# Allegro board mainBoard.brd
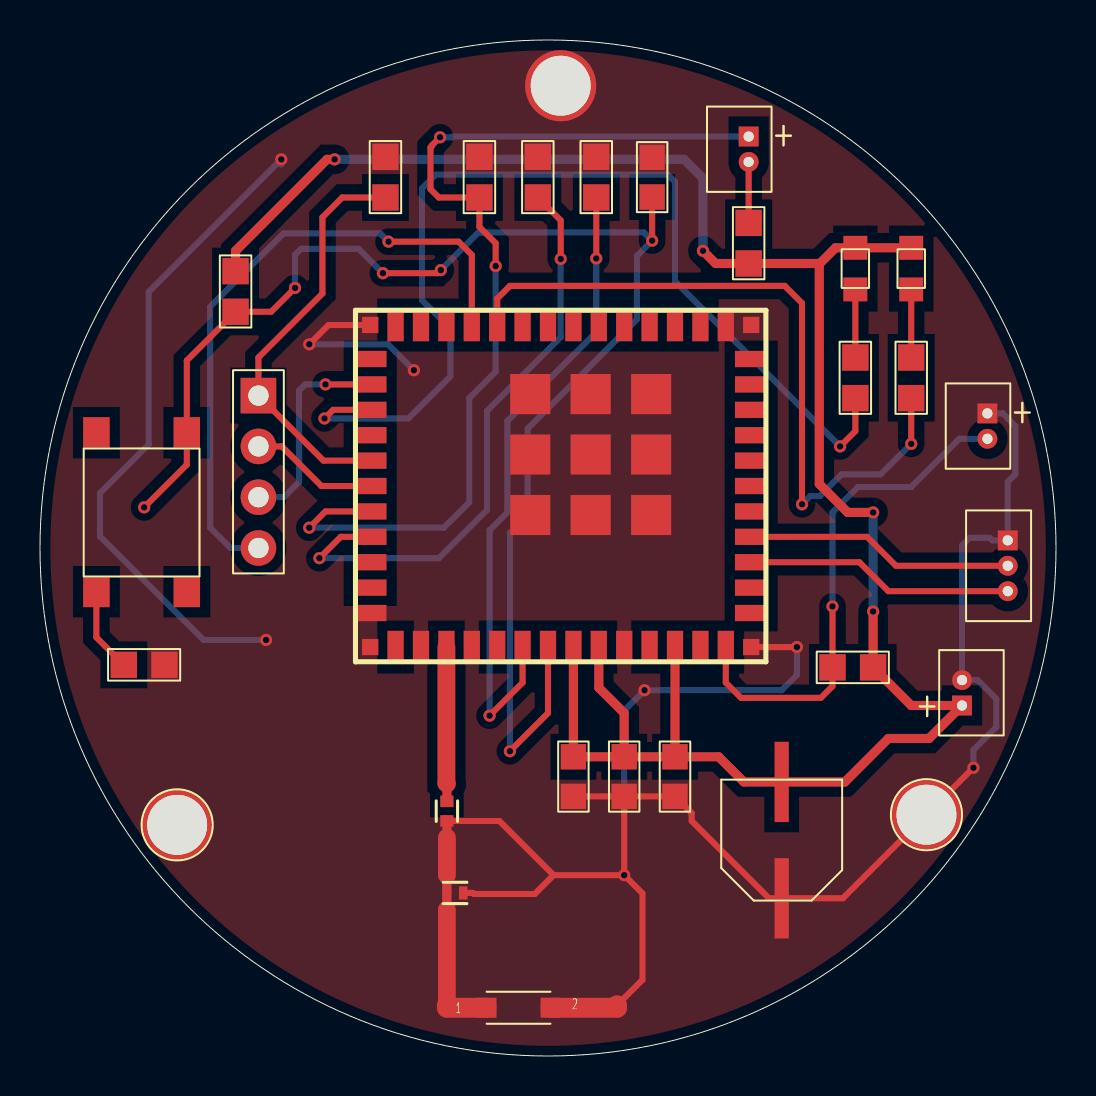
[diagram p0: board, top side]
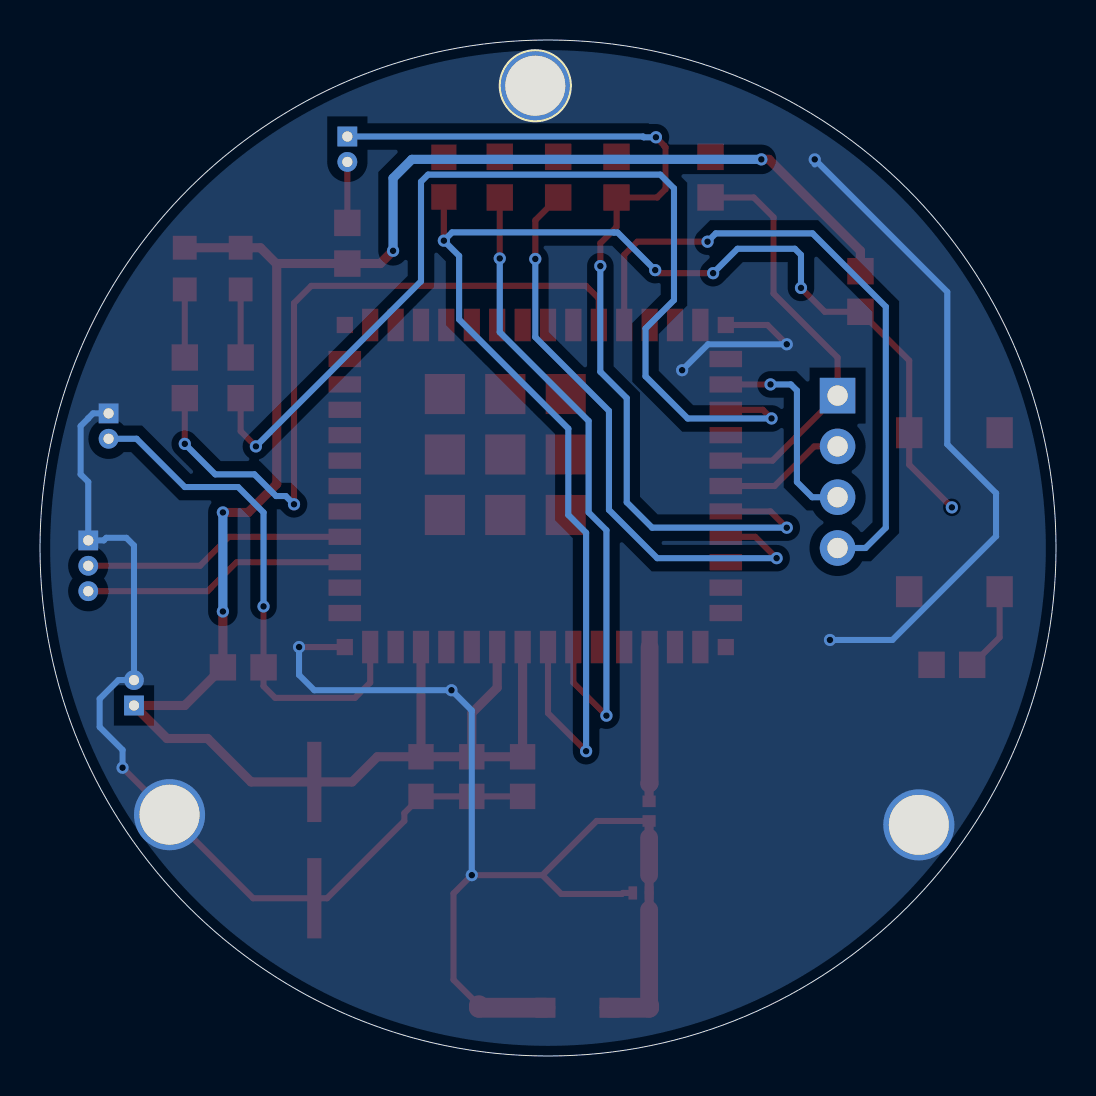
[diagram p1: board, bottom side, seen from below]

Outline 50.8 x 50.8 mm; copper layers: TOP, BOTTOM. Coordinates in mm from the lower left corner of the outline.
Outline path: circle c25.4,25.4 r25.4

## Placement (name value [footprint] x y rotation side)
C1  220uF/16V  [CAPPOL220U16V]  37.08 10.79 0 top
C2  0.1uF  [SMC0805]  29.21 13.97 270 top
C3  0.1uF  [SMC0805]  31.75 13.97 270 top
C4  1pF  [INDC_0402CS]  20.75 8.15 0 top
C5  0.1uF  [SMC0805]  30.61 43.94 90 top
C6  0.1uF  [SMC0805]  26.67 13.97 270 top
D1  -  [LED]  43.56 39.37 270 top
D2  -  [LED]  40.77 39.37 270 top
J1  HEADER 2  [HEADER21P25MM]  47.37 31.5 0 top
J2  HEADER 3  [HEADER31P25MM]  48.39 24.51 0 top
J3  HEADER 4  [HEADER42P54MM]  10.92 29.21 0 top
J4  HEADER 2  [HEADER21P25MM]  35.43 45.34 0 top
J5  HEADER 2  [HEADER21P25MM]  46.1 18.16 180 top
J6  HEADER 1  [HOLD]  44.32 12.06 0 top
J7  HEADER 1  [HOLD]  6.86 11.56 0 top
J8  HEADER 1  [HOLD]  26.04 48.51 180 bottom
L1  3.6nH  [CC0402]  20.35 12.24 270 top
R1  75  [SMR0805]  43.56 33.91 90 top
R2  75  [SMR0805]  40.77 33.91 90 top
R3  4.7K  [SMR0805]  9.78 38.23 270 top
R4  100R  [SMR0805]  5.21 19.56 0 top
R5  4.7K  [SMR0805]  35.43 40.64 90 top
R6  4.7K  [SMR0805]  40.64 19.43 180 top
R7  100K  [SMR0805]  17.27 43.94 90 top
R8  2.7K  [SMR0805]  21.97 43.94 90 top
R9  100K  [SMR0805]  24.89 43.94 90 top
R10  100K  [SMR0805]  27.81 43.94 90 top
S1  SW PUSHBUTTON  [BUTTON]  5.08 27.18 270 top
U1  -  [CC3200MOD]  35.56 20.45 0 top
U2  2.45-GHz Ant  [ANT_AH316M]  23.93 2.41 0 top

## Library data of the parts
C1 = CAPACITOR POL
C2-C6 = CAP NP
D1 D2 = LED_0
J1 J4 J5 = HEADER 2
J2 = HEADER 3
J3 = HEADER 4
J6-J8 = HEADER 1
L1 = INDUCTOR
R1-R4 R7-R10 = RESISTOR_0
R5 R6 = R
S1 = SW PUSHBUTTON
U1 = CC3200MOD_0
U2 = 2_0.45-GHz Ant

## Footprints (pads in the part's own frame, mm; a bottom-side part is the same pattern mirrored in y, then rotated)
ANT_AH316M
  rect 1.001x1.001 smd: 1(-1.6,0) 2(1.6,0)
BUTTON
  rect 1.549x1.321 smd: (-3.988,-2.261) (3.962,2.261) 1(-3.988,2.261) 2(3.962,-2.261)
CAPPOL220U16V
  rect 0.711x4.013 smd: 1(0,2.908) 2(0,-2.908)
CC0402
  rect 0.579x0.66 smd: 1(-0.49,0) 2(0.49,0)
CC3200MOD
  rect 0.813x0.813 smd: 1(0,16.104) 16(-19.05,16.104) 28(-19.05,0) 43(0,0)
  rect 0.813x1.626 smd: 2(-1.27,16.104) 3(-2.54,16.104) 4(-3.81,16.104) 5(-5.08,16.104) 6(-6.35,16.104) 7(-7.62,16.104) 8(-8.89,16.104) 9(-10.16,16.104) 10(-11.43,16.104) 11(-12.7,16.104) 12(-13.97,16.104) 13(-15.24,16.104) 14(-16.51,16.104) 15(-17.78,16.104) 29(-17.78,0) 30(-16.51,0) 31(-15.24,0) 32(-13.97,0) 33(-12.7,0) 34(-11.43,0) 35(-10.16,0) 36(-8.89,0) 37(-7.62,0) 38(-6.35,0) 39(-5.08,0) 40(-3.81,0) 41(-2.54,0) 42(-1.27,0)
  rect 1.626x0.813 smd: 17(-19.05,14.402) 18(-19.05,13.132) 19(-19.05,11.862) 20(-19.05,10.592) 21(-19.05,9.322) 22(-19.05,8.052) 23(-19.05,6.782) 24(-19.05,5.512) 25(-19.05,4.242) 26(-19.05,2.972) 27(-19.05,1.702) 44(0,1.702) 45(0,2.972) 46(0,4.242) 47(0,5.512) 48(0,6.782) 49(0,8.052) 50(0,9.322) 51(0,10.592) 52(0,11.862) 53(0,13.132) 54(0,14.402)
  rect 2.007x2.007 smd: 55(-5.004,12.649) 56(-8.026,12.649) 57(-11.049,12.649) 58(-5.004,9.627) 59(-8.026,9.627) 60(-11.049,9.627) 61(-5.004,6.604) 62(-8.026,6.604) 63(-11.049,6.604)
HEADER21P25MM
  rect 0.991x0.991 hole 0.508: 1(0,0.635)
  round 0.991 hole 0.508: 2(0,-0.635)
HEADER31P25MM
  rect 0.991x0.991 hole 0.508: 1(0,1.27)
  round 0.991 hole 0.508: 2(0,0) 3(0,-1.27)
HEADER42P54MM
  rect 1.778x1.778 hole 1.016: 1(0,3.81)
  round 1.778 hole 1.016: 2(0,1.27) 3(0,-1.27) 4(0,-3.81)
HOLD
  round 3.556 hole 2.997: 1(0,0)
INDC_0402CS
  rect 0.432x0.66 smd: 1(-0.409,0) 2(0.409,0)
LED
  rect 1.194x1.194 smd: 1(-1.041,0) 2(1.041,0)
SMC0805
  rect 1.27x1.27 smd: 1(-0.991,0) 2(0.991,0)
SMR0805
  rect 1.321x1.321 smd: 1(-1.016,0) 2(1.016,0)

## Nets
GND: C1.2 C2.2 C3.2 C4.1 C4.2 C5.2 C6.2 J1.1 J2.1 J5.2 J6.1 J7.1 J8.1 L1.2 R4.2 R7.2 R8.2 R9.2 R10.2 U1.1(GND2) U1.2(GND1) U1.16(GND18) U1.27(GND4) U1.28(GND7) U1.30(GND3) U1.32(GND8) U1.38(GND6) U1.43(GND5) U1.55(GND17) U1.56(GND16) U1.57(GND15) U1.58(GND14) U1.59(GND13) U1.60(GND12) U1.61(GND11) U1.62(GND10) U1.63(GND9) U2.1(IN) U2.2(GND)
VCC_3.3V: C1.1 C2.1 C3.1 C6.1 D1.1 D2.1 J5.1 R3.1 R5.1 R6.1 U1.36(VBAT_DCDC_ANA) U1.37(VBAT_DCDC_PA) U1.40(VBAT_DCDC_DIG_IO)
NLINK: R1.1 U1.11(GPIO22)
NREADY: R2.1 U1.19(GPIO28)
NRESET: C5.1 R3.2 S1.1 U1.35(NRESET)
SOP2: J4.1 R8.1 U1.23(TCXO_EN/SOP2)
SWITCH: J1.2 R6.2 U1.42(GPIO30)
UART0_RX: J2.2 U1.47(GPIO2)
UART0_TX: J2.3 U1.46(GPIO1)
N01152: R4.1 S1.2
N10829: J3.1 R7.1 U1.21(JTAG_TCK)
N10833: J3.2 U1.22(JTAG_TMS)
N10837: J3.3 U1.18(JTAG_TDO)
N10841: J3.4 U1.12(JTAG_TDI)
N12921: L1.1 U1.31(RF_BG)
N18108: R10.1 U1.34(SOP0)
N18112: R9.1 U1.24(SOP1)
N33058: J4.2 R5.2
N545706: D1.2 R1.2
N545710: D2.2 R2.2

Pads without a net: U1 3 4 5 6 7 8 9 10 13 14 15 17 20 25 26 29 33 39 41 44 45 48 49 50 51 52 53 54

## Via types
v1: diameter 0.61, hole 0.33, TOP to BOTTOM, 32 vias

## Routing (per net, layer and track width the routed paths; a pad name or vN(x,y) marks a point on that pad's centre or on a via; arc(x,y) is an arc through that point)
GND: length 154.3
  TOP w0.305: C2.2 v1(29.21,9.04) ; C2.2 C6.2 ; C2.2 C3.2 32.58,12.15 32.58,11.75 36.45,7.89 C1.2 40.14,7.89 J6.1 v1(46.67,14.41) ; v1(29.21,9.04) 25.68,9.04 ; v1(29.21,9.04) 30.12,8.13 30.12,3.81 28.85,2.54 ; 25.68,9.04 24.74,8.1 21.71,8.1 21.66,8.15 C4.2 ; 25.68,9.04 22.97,11.75 L1.2 ; v1(37.85,20.45) U1.43 ; v1(13.46,35.59) 14.43,36.55 U1.16 ; 24.89,47.37 J8.1
  TOP w0.457: 20.34,7.32 C4.1 20.34,9.04 20.35,9.04 ; L1.2 20.35,10.92
  TOP w0.889: 20.34,2.54 20.34,7.32 ; 20.35,10.92 20.35,9.04
  TOP w0.991: 28.85,2.54 28.85,2.41 U2.2 ; U2.1 20.34,2.41 20.34,2.54
  BOTTOM w0.305: v1(18.69,34.29) 17.4,35.59 v1(13.46,35.59) ; J1.1 48.15,32.13 48.39,31.89 48.39,31.88 48.77,31.5 48.77,29.08 48.39,28.7 J2.1 47.61,25.78 47.49,25.91 46.48,25.91 46.1,25.53 J5.2 46.88,18.8 47.82,17.86 47.82,16.45 46.67,15.3 v1(46.67,14.41) ; v1(37.85,20.45) 37.85,19.05 37.08,18.29 v1(30.23,18.29) 29.21,17.27 v1(29.21,9.04) ; v1(11.3,20.8) 8.18,20.8 3,25.98 3,28.14 5.44,30.58 5.44,38.2 v1(12.06,44.83) 12.06,44.58
VCC_3.3V: length 107.1
  TOP w0.457: 38.96,39.6 39.78,40.41 D2.1 D1.1 ; 38.96,39.6 38.94,39.62 R5.1 33.78,39.62 v1(33.15,40.26) ; 38.96,39.6 38.96,28.6 40.39,27.18 v1(41.66,27.18) ; U1.40 C3.1 ; C3.1 33.93,14.96 35.19,13.7 C1.1 40.25,13.7 42.42,15.87 44.45,15.87 J5.1 43.56,17.53 R6.1 v1(41.66,22.22) ; C3.1 C2.1 ; C2.1 29.21,17.14 27.94,18.41 U1.37 ; C2.1 C6.1 U1.36 ; v1(14.73,44.83) 14.35,44.83 9.78,40.26 R3.1
  BOTTOM w0.457: v1(14.73,44.83) 32.21,44.83 33.15,43.89 v1(33.15,40.26) ; v1(41.66,22.22) v1(41.66,27.18)
NLINK: length 36.2
  TOP w0.305: U1.11 22.86,37.87 23.49,38.51 37.24,38.51 38.1,37.64 v1(38.1,27.58) ; v1(43.56,30.61) R1.1
  BOTTOM w0.305: v1(43.56,30.61) 42.04,29.08 40.08,29.08 39,28 38.51,28 v1(38.1,27.58)
NREADY: length 52.1
  TOP w0.305: v1(14.22,31.88) 14.66,32.31 U1.19 ; v1(40,30.48) 40.77,31.24 R2.1
  BOTTOM w0.305: v1(14.22,31.88) 18.41,31.88 20.52,33.99 20.52,36.37 19.1,37.8 19.1,43.38 19.79,44.07 31.39,44.07 31.75,43.71 31.75,38.73 v1(40,30.48)
NRESET: length 72.9
  TOP w0.305: U1.35 25.4,17.14 v1(23.49,15.24) ; v1(30.61,40.77) C5.1 ; v1(17.14,39.14) 19.89,39.14 v1(20.04,39.29) ; v1(5.21,27.43) 7.34,29.57 S1.1 7.34,34.77 R3.2 11.56,37.21 v1(12.75,38.4)
  BOTTOM w0.305: v1(20.04,39.29) 21.92,41.17 22.1,41.17 22.11,41.18 30.19,41.18 v1(30.61,40.77) 29.84,40 29.84,36.83 24.38,31.37 24.38,27.05 23.49,26.16 v1(23.49,15.24) ; v1(12.75,38.4) 12.75,40.06 13.06,40.36 15.93,40.36 v1(17.14,39.14)
SOP2: length 48.9
  TOP w0.305: v1(13.46,26.42) 14.27,27.23 U1.23 ; v1(20,45.94) 19.59,45.52 19.59,45.5 19.52,45.43 19.52,43.34 19.94,42.93 R8.1 21.97,41.45 22.78,40.64 v1(22.78,39.5)
  BOTTOM w0.305: J4.1 20.65,45.97 20.61,45.94 v1(20,45.94) ; v1(13.46,26.42) 20.19,26.42 21.46,27.69 21.46,32.89 22.78,34.21 v1(22.78,39.5)
SWITCH: length 25.6
  TOP w0.305: U1.42 34.29,18.67 35.05,17.91 39.04,17.91 39.62,18.49 R6.2 v1(39.62,22.48)
  BOTTOM w0.305: J1.2 45.97,30.86 43.56,28.45 40.89,28.45 39.62,27.18 v1(39.62,22.48)
UART0_RX: length 13.4
  TOP w0.305: J2.2 42.8,24.51 41.35,25.96 U1.47
UART0_TX: length 13.4
  TOP w0.305: U1.46 40.97,24.69 42.42,23.24 J2.3
N01152: length 4.2
  TOP w0.305: S1.2 2.82,20.93 4.19,19.56
N10829: length 20.7
  TOP w0.305: R7.1 15.11,42.93 14.12,41.94 14.12,38.13 10.92,34.92 J3.1 14.17,29.77 U1.21
N10833: length 6.4
  TOP w0.305: J3.2 12.09,30.48 14.07,28.5 U1.22
N10837: length 10.6
  TOP w0.305: U1.18 v1(14.27,33.58)
  BOTTOM w0.305: J3.3 12.19,27.94 12.95,28.7 12.95,33.27 13.26,33.58 v1(14.27,33.58)
N10841: length 32.4
  TOP w0.305: v1(17.42,40.72) 20.93,40.72 21.59,40.06 U1.12
  BOTTOM w0.305: J3.4 9.52,25.4 8.51,26.42 8.51,37.46 12.17,41.13 17.01,41.13 v1(17.42,40.72)
N12921: length 7.7
  TOP w0.457: 20.35,13.61 L1.1
  TOP w0.889: 20.35,13.61 20.32,13.64 U1.31
N18108: length 32.2
  TOP w0.305: U1.34 24.13,18.67 v1(22.48,17.02) ; v1(27.81,39.88) R10.1
  BOTTOM w0.305: v1(22.48,17.02) 22.48,26.29 23.37,27.18 23.37,31.75 27.81,36.2 v1(27.81,39.88)
N18112: length 30
  TOP w0.305: v1(26.04,39.85) 26.04,41.78 R9.1 ; v1(13.97,24.89) 15.04,25.96 U1.24
  BOTTOM w0.305: v1(13.97,24.89) 19.94,24.89 22.35,27.3 22.35,32.26 26.04,35.94 v1(26.04,39.85)
N33058: length 3
  TOP w0.305: R5.2 J4.2
N545706: length 3.4
  TOP w0.305: R1.2 D1.2
N545710: length 3.4
  TOP w0.305: R2.2 D2.2

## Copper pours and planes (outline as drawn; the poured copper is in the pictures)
GND on TOP: 0.51,25.4 50.29,25.4 ; 4 cut-outs
GND on BOTTOM: 0.51,25.4 50.29,25.4 ; 3 cut-outs
